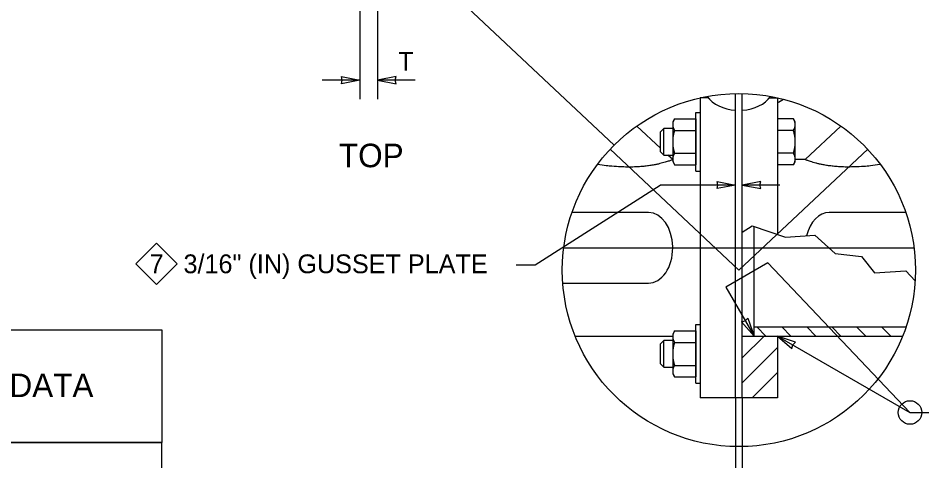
# Model space of a CAD drawing. Extents: x 99862 to 104211, y 98939 to 111076.
# Drawn here: x 101228 to 101996, y 106519 to 106895 of the extents above; entities that cross this region are included whole.
import ezdxf

# ---------------------------------------------------------------- set-up
doc = ezdxf.new("R2010")
doc.units = 0
for name, color, linetype in [('Level 12', 7, 'Continuous'), ('Level 13', 7, 'Continuous'), ('Level 14', 7, 'Continuous'), ('Level 15', 7, 'Continuous'), ('Level 20', 7, 'Continuous'), ('Level 4', 7, 'Continuous'), ('Level 40', 7, 'Continuous'), ('Level 5', 7, 'Continuous'), ('Level 7', 7, 'Continuous'), ('Level 9', 7, 'Continuous')]:
    doc.layers.add(name, color=color, linetype=linetype)

msp = doc.modelspace()

# ---------------------------------------------------------------- linework, layer by layer
at = {"layer": 'Level 12'}
for p, q in [((101837.48, 106572.6), (101837.48, 106831.23)), ((101843.1, 106572.6), (101843.1, 106831.23)), ((101853.1, 106625.1), (101853.1, 106718.38))]:
    msp.add_line(p, q, dxfattribs=at)
at = {"layer": 'Level 13'}
for p, q in [((101807.48, 106827.6), (101807.48, 106572.6)), ((101814.31, 106827.6), (101807.48, 106827.6)), ((101873.1, 106572.6), (101807.48, 106572.6))]:
    msp.add_line(p, q, dxfattribs=at)
at = {"layer": 'Level 14'}
for p, q in [((101866.27, 106827.6), (101873.1, 106827.6)), ((101873.1, 106827.6), (101873.1, 106711.47)), ((101873.1, 106625.1), (101873.1, 106572.6))]:
    msp.add_line(p, q, dxfattribs=at)
at = {"layer": 'Level 15'}
for p, q in [((101587.6, 106925.15), (101734.16, 106787.29)), ((101533.14, 106923.93), (101533.14, 106826.65)), ((101518.14, 106907.93), (101518.14, 106826.65)), ((101518.14, 106842.65), (101486.14, 106842.65)), ((101565.14, 106842.65), (101533.14, 106842.65)), ((101874.03, 106823.85), (101878.06, 106826.42)), ((101840.28, 106681.17), (101730.85, 106783.88)), ((101840.28, 106681.17), (101949.72, 106783.88)), ((101667.05, 106685.63), (101773.48, 106753.52)), ((101837.48, 106753.52), (101773.48, 106753.52)), ((101875.1, 106753.52), (101843.1, 106753.52)), ((101691.4, 106700.1), (101989.17, 106700.1)), ((101864.75, 106687.25), (101829.1, 106666.67)), ((101985.68, 106560.1), (101864.75, 106687.25)), ((101651.05, 106685.63), (101667.05, 106685.63)), ((101829.1, 106666.67), (101853.1, 106625.1)), ((101873.1, 106625.1), (101985.68, 106560.1)), ((101837.48, 106572.6), (101837.48, 106428.1)), ((101843.1, 106572.6), (101843.1, 106428.1)), ((101985.68, 106560.1), (102033.68, 106560.1))]:
    msp.add_line(p, q, dxfattribs=at)
for points in [[(101518.14, 106842.65), (101502.41, 106839.56), (101503.14, 106842.65), (101502.41, 106845.73)], [(101533.14, 106842.65), (101548.86, 106839.56), (101548.13, 106842.65), (101548.86, 106845.73)], [(101837.48, 106753.52), (101821.75, 106750.43), (101822.48, 106753.52), (101821.75, 106756.6)], [(101843.1, 106753.52), (101858.83, 106750.43), (101858.1, 106753.52), (101858.83, 106756.6)], [(101853.1, 106625.1), (101842.57, 106637.18), (101845.6, 106638.09), (101847.91, 106640.26)], [(101873.1, 106625.1), (101885.18, 106614.57), (101886.09, 106617.6), (101888.26, 106619.91)]]:
    msp.add_lwpolyline(points, close=True, dxfattribs=at)
for centre, radius in [((101840.28, 106681.17), 150.09), ((101985.68, 106560.1), 10)]:
    msp.add_circle(centre, radius, dxfattribs=at)
at = {"layer": 'Level 20'}
msp.add_lwpolyline([(101345.31, 106704.06), (101362.87, 106686.51), (101345.31, 106668.95), (101327.76, 106686.51)], close=True, dxfattribs=at)
at = {"layer": 'Level 4'}
for p, q in [((101896.53, 106775.1), (101888.1, 106775.1)), ((101763.51, 106730.1), (101698.4, 106730.1)), ((101982.17, 106730.1), (101917.06, 106730.1)), ((101690.61, 106670.1), (101763.51, 106670.1)), ((101853.1, 106632.9), (101982.4, 106632.9)), ((101863.29, 106625.1), (101855.49, 106632.9)), ((101884.5, 106625.1), (101876.7, 106632.9)), ((101905.71, 106625.1), (101897.91, 106632.9)), ((101926.93, 106625.1), (101919.13, 106632.9)), ((101948.14, 106625.1), (101940.34, 106632.9)), ((101969.35, 106625.1), (101961.55, 106632.9)), ((101701.06, 106625.1), (101784.04, 106625.1)), ((101843.1, 106606.45), (101861.75, 106625.1)), ((101843.1, 106625.1), (101979.51, 106625.1)), ((101843.1, 106585.24), (101873.1, 106615.24)), ((101851.67, 106572.6), (101873.1, 106594.03)), ((101872.89, 106572.6), (101873.1, 106572.82))]:
    msp.add_line(p, q, dxfattribs=at)
msp.add_lwpolyline([(101843.1, 106713.47), (101851.48, 106718.94), (101879.76, 106709.16), (101904.9, 106710.91), (101922.01, 106695.2), (101944.36, 106692.75), (101955.53, 106678.79), (101982.06, 106680.53), (101990.09, 106671.92)], dxfattribs=at)
for centre, start_param, end_param in [((101763.51, 106700.1), 1.602826, 3.141593), ((101917.06, 106700.1), 3.141593, 4.361403), ((101763.51, 106700.1), 0, 1.570887), ((101763.51, 106700.1), 1.570887, 1.602826)]:
    msp.add_ellipse(centre, major_axis=(0, -30), ratio=0.684332, start_param=start_param, end_param=end_param, dxfattribs=at)
for points in [[(101784.04, 106775.1), (101784.04, 106775.1), (101783.98, 106775.08), (101783.87, 106775.04), (101783.55, 106774.91), (101782.73, 106774.6), (101781.49, 106774.16), (101780.24, 106773.73), (101778.52, 106773.16), (101776.48, 106772.58), (101774.37, 106771.99), (101771.86, 106771.37), (101769.15, 106770.84), (101765.52, 106770.13), (101761.46, 106769.57), (101757.33, 106769.24), (101751.52, 106768.78), (101745.43, 106768.74), (101739.54, 106769.01), (101732.85, 106769.32), (101726.19, 106770.02), (101719.97, 106770.89)], [(101960.6, 106770.89), (101953.65, 106769.92), (101946.14, 106769.16), (101938.63, 106768.92), (101933.21, 106768.75), (101927.67, 106768.85), (101922.37, 106769.31), (101918.41, 106769.66), (101914.52, 106770.22), (101911.05, 106770.91), (101908.15, 106771.49), (101905.49, 106772.17), (101903.31, 106772.81), (101901.13, 106773.44), (101899.38, 106774.05), (101898.23, 106774.46), (101897.18, 106774.85), (101896.6, 106775.07), (101896.54, 106775.1), (101896.54, 106775.1), (101896.53, 106775.1), (101896.53, 106775.1)]]:
    msp.add_open_spline(points, degree=3, dxfattribs=at)
at = {"layer": 'Level 40'}
for p in [(100881.41, 106534.52), (101349.86, 106310.52)]:
    msp.add_line(p, (101349.86, 106534.52), dxfattribs=at)
msp.add_lwpolyline([(100881.41, 106630.52), (101349.86, 106630.52), (101349.86, 106534.52), (100881.41, 106534.52)], close=True, dxfattribs=at)
at = {"layer": 'Level 5'}
for p, q in [((101773.73, 106784.78), (101753.58, 106803.68)), ((101926.99, 106803.68), (101896.53, 106775.1)), ((101784.04, 106775.1), (101779.87, 106779.01)), ((101784.04, 106775.1), (101784.04, 106775.1)), ((101896.53, 106775.1), (101896.53, 106775.1))]:
    msp.add_line(p, q, dxfattribs=at)
at = {"layer": 'Level 7'}
for start_param, end_param in [(0.458272, 1.476908), (1.664684, 2.683257)]:
    msp.add_ellipse((101840.29, 106838.21), major_axis=(-30, 0), ratio=0.707107, start_param=start_param, end_param=end_param, dxfattribs=at)
at = {"layer": 'Level 9'}
for p, q in [((101785.54, 106809.74), (101784.04, 106807.13)), ((101785.54, 106809.74), (101803.73, 106809.74)), ((101803.73, 106815.26), (101807.48, 106815.26)), ((101803.73, 106765.26), (101803.73, 106815.26)), ((101803.73, 106809.74), (101803.73, 106800)), ((101886.59, 106809.73), (101873.1, 106809.73)), ((101888.1, 106807.12), (101886.59, 106809.73)), ((101776.38, 106801.51), (101773.73, 106798.86)), ((101776.38, 106779.01), (101776.38, 106801.51)), ((101784.04, 106801.51), (101776.38, 106801.51)), ((101784.04, 106807.13), (101784.04, 106805.1)), ((101784.04, 106805.1), (101784.04, 106804.64)), ((101784.04, 106804.64), (101784.04, 106790.67)), ((101888.1, 106804.97), (101888.1, 106807.12)), ((101888.1, 106804.74), (101888.1, 106804.97)), ((101888.1, 106790.66), (101888.1, 106804.74)), ((101773.73, 106781.66), (101773.73, 106798.86)), ((101785.54, 106800), (101803.73, 106800)), ((101803.73, 106800), (101803.73, 106780.51)), ((101886.59, 106799.99), (101873.1, 106799.99)), ((101784.04, 106790.67), (101784.04, 106789.84)), ((101784.04, 106789.84), (101784.04, 106775.76)), ((101888.1, 106789.83), (101888.1, 106790.66)), ((101888.1, 106775.86), (101888.1, 106789.83)), ((101773.73, 106781.66), (101776.38, 106779.01)), ((101776.38, 106779.01), (101784.04, 106779.01)), ((101785.54, 106780.51), (101803.73, 106780.51)), ((101803.73, 106780.51), (101803.73, 106770.77)), ((101886.6, 106780.5), (101873.1, 106780.5)), ((101784.04, 106775.76), (101784.04, 106775.53)), ((101784.04, 106775.53), (101784.04, 106773.38)), ((101784.04, 106773.38), (101785.55, 106770.77)), ((101785.55, 106770.77), (101803.73, 106770.77)), ((101886.59, 106770.76), (101873.1, 106770.76)), ((101886.59, 106770.76), (101888.1, 106773.37)), ((101888.1, 106775.4), (101888.1, 106775.86)), ((101888.1, 106773.37), (101888.1, 106775.4)), ((101803.73, 106765.26), (101807.48, 106765.26)), ((101803.73, 106584.94), (101803.73, 106634.94)), ((101803.73, 106634.94), (101807.48, 106634.94)), ((101785.54, 106629.42), (101784.04, 106626.82)), ((101784.04, 106626.82), (101784.04, 106624.78)), ((101784.04, 106624.78), (101784.04, 106624.32)), ((101785.54, 106629.42), (101803.73, 106629.42)), ((101803.73, 106629.42), (101803.73, 106619.68)), ((101776.38, 106621.19), (101773.73, 106618.54)), ((101773.73, 106601.35), (101773.73, 106618.54)), ((101776.38, 106598.69), (101776.38, 106621.19)), ((101784.04, 106621.19), (101776.38, 106621.19)), ((101784.04, 106624.32), (101784.04, 106610.36)), ((101785.54, 106619.68), (101803.73, 106619.68)), ((101803.73, 106619.68), (101803.73, 106600.2)), ((101784.04, 106610.36), (101784.04, 106609.53)), ((101784.04, 106609.53), (101784.04, 106595.44)), ((101773.73, 106601.35), (101776.38, 106598.69)), ((101776.38, 106598.69), (101784.04, 106598.69)), ((101784.04, 106595.44), (101784.04, 106595.22)), ((101784.04, 106595.22), (101784.04, 106593.07)), ((101785.54, 106600.2), (101803.73, 106600.2)), ((101803.73, 106600.2), (101803.73, 106590.46)), ((101784.04, 106593.07), (101785.55, 106590.46)), ((101785.55, 106590.46), (101803.73, 106590.46)), ((101803.73, 106584.94), (101807.48, 106584.94))]:
    msp.add_line(p, q, dxfattribs=at)
for points in [[(101785.54, 106809.74), (101784.66, 106808.22), (101784.09, 106806.68), (101784.04, 106805.1)], [(101785.38, 106809.45), (101785.43, 106809.55), (101785.49, 106809.64), (101785.54, 106809.74)], [(101888.1, 106804.97), (101888.07, 106806.59), (101887.49, 106808.17), (101886.59, 106809.73)], [(101784.04, 106804.64), (101784.09, 106803.06), (101784.67, 106801.51), (101785.54, 106800)], [(101886.59, 106799.99), (101887.49, 106801.54), (101888.07, 106803.12), (101888.1, 106804.74)], [(101785.54, 106800), (101784.67, 106796.96), (101784.08, 106793.82), (101784.04, 106790.67)], [(101888.1, 106790.66), (101888.05, 106793.82), (101887.47, 106796.97), (101886.59, 106799.99)], [(101784.04, 106789.84), (101784.08, 106786.68), (101784.67, 106783.53), (101785.54, 106780.51)], [(101886.6, 106780.5), (101887.47, 106783.54), (101888.05, 106786.68), (101888.1, 106789.83)], [(101785.54, 106780.51), (101784.64, 106778.96), (101784.06, 106777.38), (101784.04, 106775.76)], [(101888.1, 106775.86), (101888.05, 106777.44), (101887.47, 106778.99), (101886.6, 106780.5)], [(101784.04, 106775.53), (101784.06, 106773.91), (101784.65, 106772.33), (101785.55, 106770.77)], [(101886.59, 106770.76), (101887.47, 106772.28), (101888.05, 106773.82), (101888.1, 106775.4)], [(101886.76, 106771.05), (101886.7, 106770.96), (101886.65, 106770.86), (101886.59, 106770.76)], [(101785.54, 106629.42), (101784.66, 106627.9), (101784.09, 106626.36), (101784.04, 106624.78)], [(101785.38, 106629.14), (101785.43, 106629.23), (101785.49, 106629.33), (101785.54, 106629.42)], [(101784.04, 106624.32), (101784.09, 106622.74), (101784.67, 106621.2), (101785.54, 106619.68)], [(101785.54, 106619.68), (101784.67, 106616.65), (101784.08, 106613.51), (101784.04, 106610.36)], [(101784.04, 106609.53), (101784.08, 106606.37), (101784.67, 106603.22), (101785.54, 106600.2)], [(101785.54, 106600.2), (101784.64, 106598.64), (101784.06, 106597.06), (101784.04, 106595.44)], [(101784.04, 106595.22), (101784.06, 106593.6), (101784.65, 106592.01), (101785.55, 106590.46)]]:
    msp.add_open_spline(points, degree=2, dxfattribs=at)

# ---------------------------------------------------------------- texts
at = {"layer": 'Level 15'}
msp.add_text('3/16" (IN) GUSSET PLATE', height=16, dxfattribs=at).set_placement((101368.24, 106678.51))
at = {"layer": 'Level 20'}
for s, height, p in [('T', 16, (101550.76, 106850.65)), ('TOP', 20, (101500.34, 106768.65)), ('7', 16, (101339.37, 106678.51))]:
    msp.add_text(s, height=height, dxfattribs=at).set_placement(p)
msp.add_text('CHORD FIELD SPLICE DATA', height=20, rotation=360, dxfattribs=at).set_placement((100929.05, 106573.19))

doc.saveas('drawing.dxf')
